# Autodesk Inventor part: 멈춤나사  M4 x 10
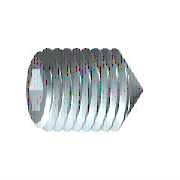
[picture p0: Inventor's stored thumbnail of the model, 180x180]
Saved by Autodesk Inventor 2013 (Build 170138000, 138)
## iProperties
Created: 2012-02
Part Number: 멈춤나사  M4 x 10
Material: 강철, 연강
Description: 6각 소켓 머리 없는 멈춤 나사
Document SubType Name: Modeling
Standard: KS B 1028
Designer: mduedu
Standards Organization: KS
Language: ko-KR
Size Designation: 원추점 M4x10
Categories: <MemberInstance><Categories><Category DisplayName="조임쇠" InternalName="e4da775c-781d-43d5-af7c-5136215cf5a6" Mnemonic="FSTN"><Category DisplayName="볼트" InternalN
Density: 7.86 g/cm^3
Mass: 0.792069 g
Surface Area: 1.48192 cm^2
Volume: 0.100772 cm^3
Author: mduedu
IsCustomPart: 1
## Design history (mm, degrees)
sketch "스케치1"
  geometry: L1 (0, 0)-(6.833, 0); L2 (10, 1.155)-(10, 2); L3 (10, 2)-(0, 2); L4 (10, 1.155)-(7.5, 1.155); L5 (7.5, 1.155)-(6.833, 0); L6 (0, -0.4)-(0, 2.4) reference; L7 (0, 2)-(0, 0)
  constraints: 13 end point, 3 parallel, 1 collinear, 1 perpendicular, 1 point on line
  dimensions: "d0" = 2.5 distance of L2.start L4.end (= INTI); "d1" = 60 deg angle of L5 L1; "d2" = 4 diameter of L3 L1 (= NND); "d3" = 2.3094 diameter of L4 L1 (= 1.1547 x SW); "d5" = 10 distance from line of L2 L3.end (= NLG)
revolve "본체" sketch "스케치1" stored, may be unused: angle "d6" = 90 deg
sketch "스케치2"
  geometry: L1 (-0.577, 1)-(0.577, 1); L2 (0.577, 1)-(1.155, 0); L3 (1.155, 0)-(0.577, -1); L4 (0.577, -1)-(-0.577, -1); L5 (-0.577, -1)-(-1.155, 0); L6 (-1.155, 0)-(-0.577, 1); 3 further points
  constraints: 12 end point, 1 coincident, 1 horizontal, 13 other
extrude "슬롯" join sketch "스케치2" taper "d7" = 0 deg; stored distance "d21" = 10
workaxis "Work Axis1"
workplane "Work Plane1"
sketch "스케치4"
  geometry: L1 (-5, 0.2)-(-3.2, 2) reference; L2 (-5, -0.2)-(-3.2, -2) reference; L3 (-3.2, 2)-(-5.2, 0); L4 (-3.2, -2)-(-5.2, 0); 2 further points
  constraints: 4 end point, 2 collinear, 1 coincident
body "Solid1"
feature "스레드" dims "d12" = 10 (= NLG), "d13" = 0
chamfer "모따기1" distance "d8" = 1.8 (computed from NND, SPD, FAWI); stored, may be unused: angle "d9" = 45 deg (= FAWI), second distance "d34" = 1.8 (computed from NND, SPD, FAWI)
chamfer "모따기2" distance "d10" = 0.42941 (= -0.5 x GD1 + 0.5 x NND); stored, may be unused: angle "d11" = 45 deg (= FAWI), second distance "d35" = 0.42941 (= -0.5 x GD1 + 0.5 x NND)
other parameters: "NND" = 4 [user parameter; used in 5 equation terms], "NLG" = 10 [user parameter; used in 2 equation terms], "INTI" = 2.5 [user parameter; used in 1 equation term], "FAWI" = 45 deg [user parameter; used in 4 equation terms], "SW" = 2 [user parameter; used in 2 equation terms], "GD1" = 3.14117 (= THREADDIA - 1.2269 x PTC) [user parameter; used in 2 equation terms], "d4" = 0, "FAWI1" = 45 deg [user parameter], "SPD" = 0.4 [user parameter; used in 2 equation terms], "d36" = 0, "d37" = 0, "GUL" = 0.42941 (= 0.61345 x PTC) [user parameter], "TPU" = 14.28571 (computed from PTC) [user parameter], "TOA" = 30 deg [user parameter], "THREADDIA" = 4 [user parameter; used in 1 equation term], "PTC" = 0.7 [user parameter; used in 4 equation terms], "GAL" = 0.42941 (= 0.61345 x PTC) [user parameter], "E0" = 2.31 (= 1.155 x SW) [user parameter]
